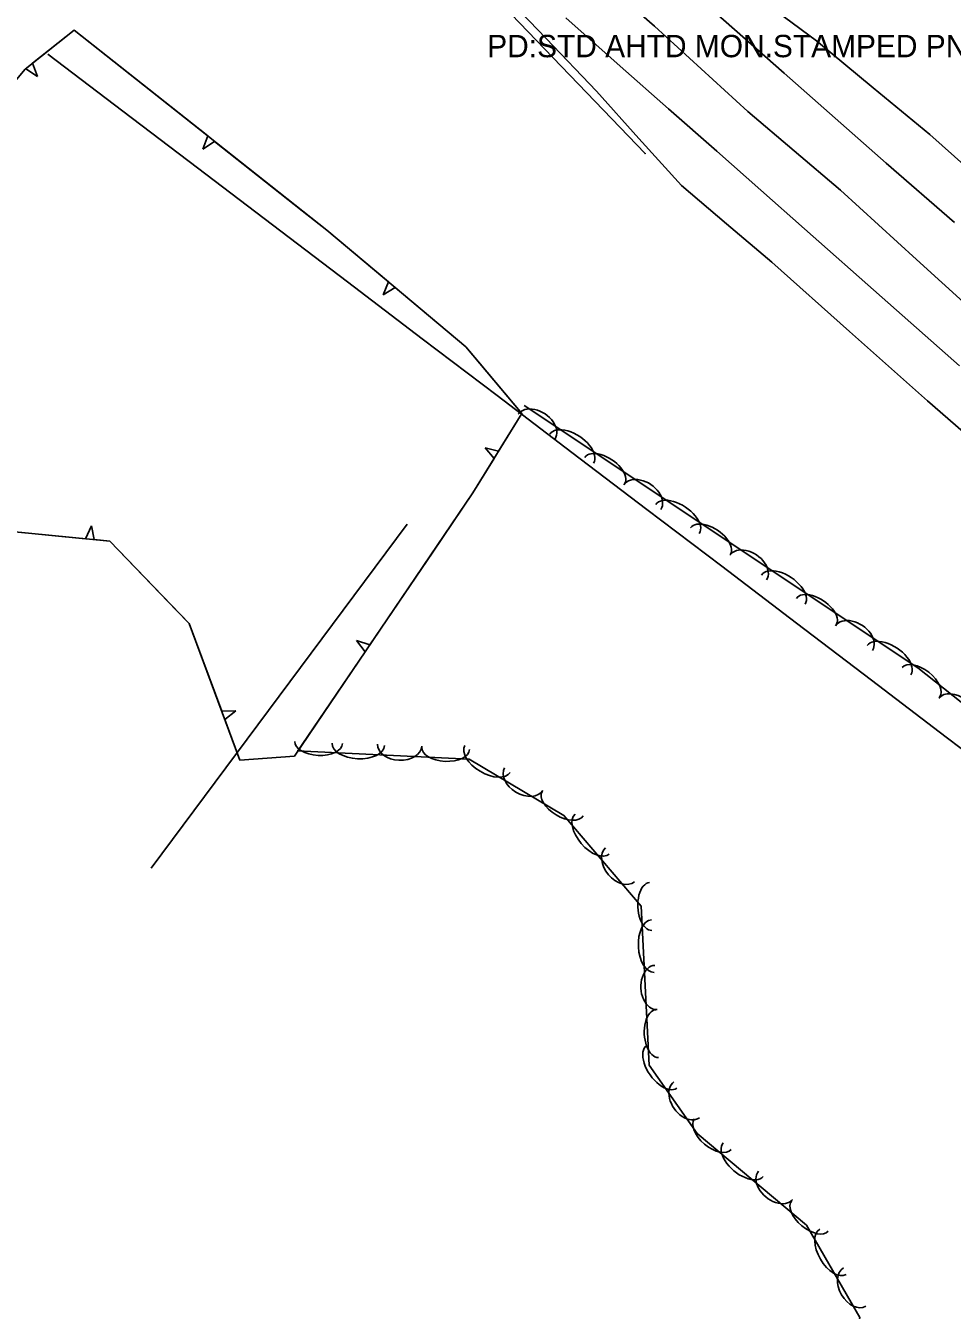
# Model space of a CAD drawing. Extents: x 1441650 to 1491889, y 345904 to 358319.
# Drawn here: x 1442949.9 to 1443157.1, y 356423.3 to 356710.4 of the extents above; entities that cross this region are included whole.
import ezdxf

# ---------------------------------------------------------------- set-up
doc = ezdxf.new("R2010")
doc.units = 0
for name, color, linetype in [('S_EDGE_PAVEMENT', 7, 'Continuous'), ('S_GUARDRAIL', 7, 'Continuous'), ('S_PAVEMENT_CROWN', 7, 'Continuous'), ('S_PRIMARY_CTL_ANNOT', 7, 'Continuous'), ('S_RDW_PT_SYM', 7, 'Continuous'), ('S_SHOULDER', 7, 'Continuous'), ('S_STREAM', 7, 'Continuous'), ('S_TREE', 7, 'Continuous')]:
    doc.layers.add(name, color=color, linetype=linetype)

msp = doc.modelspace()

# ---------------------------------------------------------------- linework, layer by layer
at = {"layer": 'S_EDGE_PAVEMENT'}
for points in [[(1443097.33, 356719.43), (1443108.42, 356709.61), (1443119.52, 356699.8), (1443130.93, 356689.75), (1443142.35, 356679.7), (1443157.61, 356666.41)], [(1443070.75, 356712.18), (1443082.9, 356701.4), (1443093.7, 356691.88), (1443104.51, 356682.36), (1443114.3, 356673.69), (1443124.08, 356665.02), (1443141.43, 356649.7), (1443158.78, 356634.38)]]:
    msp.add_lwpolyline(points, dxfattribs=at)
at = {"layer": 'S_GUARDRAIL'}
msp.add_line((1443034.47, 356738), (1443088.44, 356681.87), dxfattribs=at)
at = {"layer": 'S_PAVEMENT_CROWN'}
msp.add_lwpolyline([(1443076.96, 356722.17), (1443090.55, 356710.29), (1443100.99, 356700.76), (1443111.42, 356691.24), (1443121.76, 356682.45), (1443132.11, 356673.67), (1443149.13, 356658.19), (1443166.15, 356642.71)], dxfattribs=at)
at = {"layer": 'S_RDW_PT_SYM'}
msp.add_lwpolyline([(1443088.44, 356681.87), (1443088.44, 356681.92), (1443088.44, 356681.87), (1443088.39, 356681.87), (1443088.44, 356681.87), (1443088.44, 356681.82), (1443088.44, 356681.87), (1443088.49, 356681.87)], dxfattribs=at)
at = {"layer": 'S_SHOULDER'}
for points in [[(1443055.03, 356719.33), (1443066.3, 356707.56), (1443077.58, 356695.8), (1443087.08, 356685.25), (1443096.59, 356674.71), (1443106.67, 356666.13), (1443116.75, 356657.55), (1443134.17, 356642.06), (1443151.58, 356626.56), (1443163, 356616.65)], [(1443114.21, 356716.46), (1443126.77, 356707.03), (1443139.45, 356696.57), (1443152.14, 356686.1), (1443165.25, 356674.41)]]:
    msp.add_lwpolyline(points, dxfattribs=at)
at = {"layer": 'S_STREAM'}
msp.add_lwpolyline([(1442978, 356522.14), (1443035.24, 356598.98)], dxfattribs=at)
at = {"layer": 'S_TREE'}
for p, q in [((1442949.93, 356700.79), (1442952.54, 356699.04)), ((1442952.54, 356699.04), (1442951.47, 356702.02)), ((1442990.65, 356685.79), (1442989.52, 356682.85)), ((1442989.52, 356682.85), (1442992.19, 356684.57)), ((1443031.06, 356653.16), (1443029.86, 356650.26)), ((1443029.86, 356650.26), (1443032.57, 356651.9)), ((1443055.7, 356615.33), (1443052.65, 356616.1)), ((1443052.65, 356616.1), (1443054.67, 356613.66)), ((1442964.62, 356598.62), (1442963.3, 356595.74)), ((1442965.26, 356595.55), (1442964.62, 356598.62)), ((1443026.92, 356572.07), (1443023.91, 356572.98)), ((1443023.91, 356572.98), (1443025.82, 356570.45)), ((1442996.96, 356557.27), (1442993.79, 356557.18)), ((1442994.48, 356555.34), (1442996.96, 356557.27))]:
    msp.add_line(p, q, dxfattribs=at)
for points in [[(1442867.23, 356601.88), (1442949.79, 356700.68), (1442960.76, 356709.42), (1443017.26, 356664.74), (1443048.34, 356638.66), (1443060.91, 356623.77), (1443049.96, 356606.02), (1443010.03, 356547.18), (1442997.84, 356546.29), (1442986.49, 356576.82), (1442968.76, 356595.2), (1442946.04, 356597.46), (1442923.09, 356580.9), (1442903.27, 356562.92)], [(1442951.47, 356702.02), (1442960.76, 356709.42), (1442971.05, 356701.29)], [(1442954.88, 356704.07), (1442971.63, 356691.35), (1442988.37, 356678.63), (1443005.11, 356665.91), (1443021.86, 356653.19), (1443038.6, 356640.47), (1443055.34, 356627.75), (1443072.09, 356615.03), (1443088.83, 356602.31), (1443105.57, 356589.59), (1443122.31, 356576.87), (1443139.06, 356564.15), (1443155.8, 356551.43), (1443172.54, 356538.71), (1443189.29, 356525.99), (1443206.03, 356513.27), (1443222.77, 356500.55), (1443239.37, 356485.04), (1443255.97, 356469.54), (1443272.57, 356454.03), (1443289.17, 356438.53), (1443305.77, 356423.02)], [(1442954.88, 356704.07), (1442971.63, 356691.35), (1442988.37, 356678.63), (1443005.11, 356665.91), (1443021.86, 356653.19), (1443038.6, 356640.47), (1443055.34, 356627.75), (1443072.09, 356615.03), (1443088.83, 356602.31), (1443105.57, 356589.59), (1443122.31, 356576.87), (1443139.06, 356564.15), (1443155.8, 356551.43), (1443172.54, 356538.71), (1443189.29, 356525.99), (1443206.03, 356513.27), (1443222.77, 356500.55), (1443239.37, 356485.04), (1443255.97, 356469.54), (1443272.57, 356454.03), (1443289.17, 356438.53), (1443305.77, 356423.02)], [(1442971.05, 356701.29), (1442990.65, 356685.79)], [(1442992.19, 356684.57), (1443011.78, 356669.07)], [(1443011.78, 356669.07), (1443017.26, 356664.74), (1443031.06, 356653.16)], [(1443032.57, 356651.9), (1443048.34, 356638.66), (1443051.18, 356635.3)], [(1443051.18, 356635.3), (1443060.91, 356623.77), (1443055.7, 356615.33)], [(1443061.38, 356625.56), (1443149.42, 356566.89), (1443238.1, 356496.67), (1443329.08, 356431.82), (1443408.54, 356365.94), (1443493.9, 356292.78), (1443496.12, 356264.93), (1443483.03, 356238.12), (1443471.09, 356227.39)], [(1443054.67, 356613.66), (1443049.96, 356606.02), (1443040.96, 356592.76)], [(1442963.3, 356595.74), (1442946.04, 356597.46), (1442939.83, 356592.99)], [(1442983.68, 356579.74), (1442968.76, 356595.2), (1442965.26, 356595.55)], [(1443040.96, 356592.76), (1443026.92, 356572.07)], [(1442993.79, 356557.18), (1442986.49, 356576.82), (1442983.68, 356579.74)], [(1443025.82, 356570.45), (1443011.78, 356549.76)], [(1443011.78, 356549.76), (1443010.03, 356547.18), (1442997.84, 356546.29), (1442994.48, 356555.34)], [(1443126.51, 356367.27), (1443136.49, 356421.71), (1443124.5, 356442.34), (1443100.1, 356462.82), (1443089.39, 356478.05), (1443087.59, 356513.6), (1443070.28, 356533.9), (1443049.11, 356546.52), (1443010.64, 356548.31)]]:
    msp.add_lwpolyline(points, dxfattribs=at)
for centre, major_axis, ratio, start_param, end_param in [((1443064.18, 356620.83), (-4.12, 2.75), 0.685265, 3.141746, 6.283339), ((1443072.03, 356615.91), (-4.88, 3.25), 0.550043, 3.141686, 6.283279), ((1443079.41, 356610.99), (-4.45, 2.96), 0.540663, 3.141683, 6.283276), ((1443087.84, 356605.06), (-4.12, 2.75), 0.685265, 3.141746, 6.283339), ((1443095.69, 356600.15), (-4.88, 3.25), 0.550043, 3.141686, 6.283279), ((1443103.07, 356595.23), (-4.45, 2.96), 0.540663, 3.141683, 6.283276), ((1443111.49, 356589.3), (-4.12, 2.75), 0.685265, 3.141746, 6.283339), ((1443119.34, 356584.38), (-4.88, 3.25), 0.550043, 3.141686, 6.283279), ((1443126.72, 356579.47), (-4.45, 2.96), 0.540663, 3.141683, 6.283276), ((1443135.15, 356573.54), (-4.12, 2.75), 0.685265, 3.141746, 6.283339), ((1443143, 356568.62), (-4.88, 3.25), 0.550043, 3.141686, 6.283279), ((1443150.11, 356563.63), (-4.19, 3.32), 0.540647, 3.141593, 6.283185), ((1443158.03, 356557.03), (-3.88, 3.08), 0.685245, 3.141593, 6.283185), ((1443015.45, 356550.21), (5.34, -0.25), 0.54039, 3.141593, 6.283185), ((1443024.31, 356549.8), (5.86, -0.27), 0.549765, 3.141593, 6.283185), ((1443033.57, 356549.63), (4.95, -0.23), 0.684918, 3.141593, 6.283185), ((1443043.85, 356548.88), (5.34, -0.25), 0.54039, 3.141593, 6.283185), ((1443053.2, 356546.54), (5.04, -3), 0.54972, 3.141593, 6.283185), ((1443061.29, 356542.03), (4.26, -2.54), 0.684863, 3.141593, 6.283185), ((1443070.01, 356536.53), (4.59, -2.74), 0.540346, 3.141593, 6.283185), ((1443076.62, 356529.73), (3.81, -4.47), 0.549782, 3.141593, 6.283185), ((1443082.83, 356522.86), (3.21, -3.77), 0.68494, 3.141593, 6.283185), ((1443089.71, 356513.54), (0.27, -5.34), 0.540625, 3.14159, 6.283183), ((1443090.16, 356504.69), (0.3, -5.86), 0.550004, 3.14159, 6.283182), ((1443090.89, 356495.45), (0.25, -4.95), 0.685216, 3.141588, 6.283181), ((1443091.15, 356485.15), (0.27, -5.34), 0.540625, 3.14159, 6.283183), ((1443092.2, 356477.74), (3.37, -4.79), 0.550505, 3.140348, 6.281941), ((1443097.73, 356470.33), (2.85, -4.04), 0.685839, 3.139553, 6.281146), ((1443103.59, 356462.65), (4.09, -3.43), 0.541308, 3.140009, 6.281601), ((1443110.37, 356456.96), (4.49, -3.76), 0.550699, 3.139957, 6.28155), ((1443117.62, 356451.22), (3.8, -3.17), 0.68608, 3.138911, 6.280504), ((1443125.33, 356444.41), (4.09, -3.43), 0.541308, 3.140009, 6.281601), ((1443130.44, 356436.35), (2.95, -5.07), 0.550241, 3.140699, 6.282291), ((1443135.31, 356428.48), (2.49, -4.28), 0.685511, 3.140128, 6.28172)]:
    msp.add_ellipse(centre, major_axis=major_axis, ratio=ratio, start_param=start_param, end_param=end_param, dxfattribs=at)

# ---------------------------------------------------------------- texts
at = {"layer": 'S_PRIMARY_CTL_ANNOT'}
msp.add_text('PD:STD AHTD MON.STAMPED PN:1 JOB 050264', height=5, dxfattribs=at).set_placement((1443053.14, 356703.38))

doc.saveas('drawing.dxf')
